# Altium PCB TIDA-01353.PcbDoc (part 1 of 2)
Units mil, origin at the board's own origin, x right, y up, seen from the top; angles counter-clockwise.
Board outline 6000 x 6000 mil, 2 copper layers (Top Layer, Bottom Layer), stack 61.6 mil thick; 250 components, 122 nets, 562 pads, 165 vias.
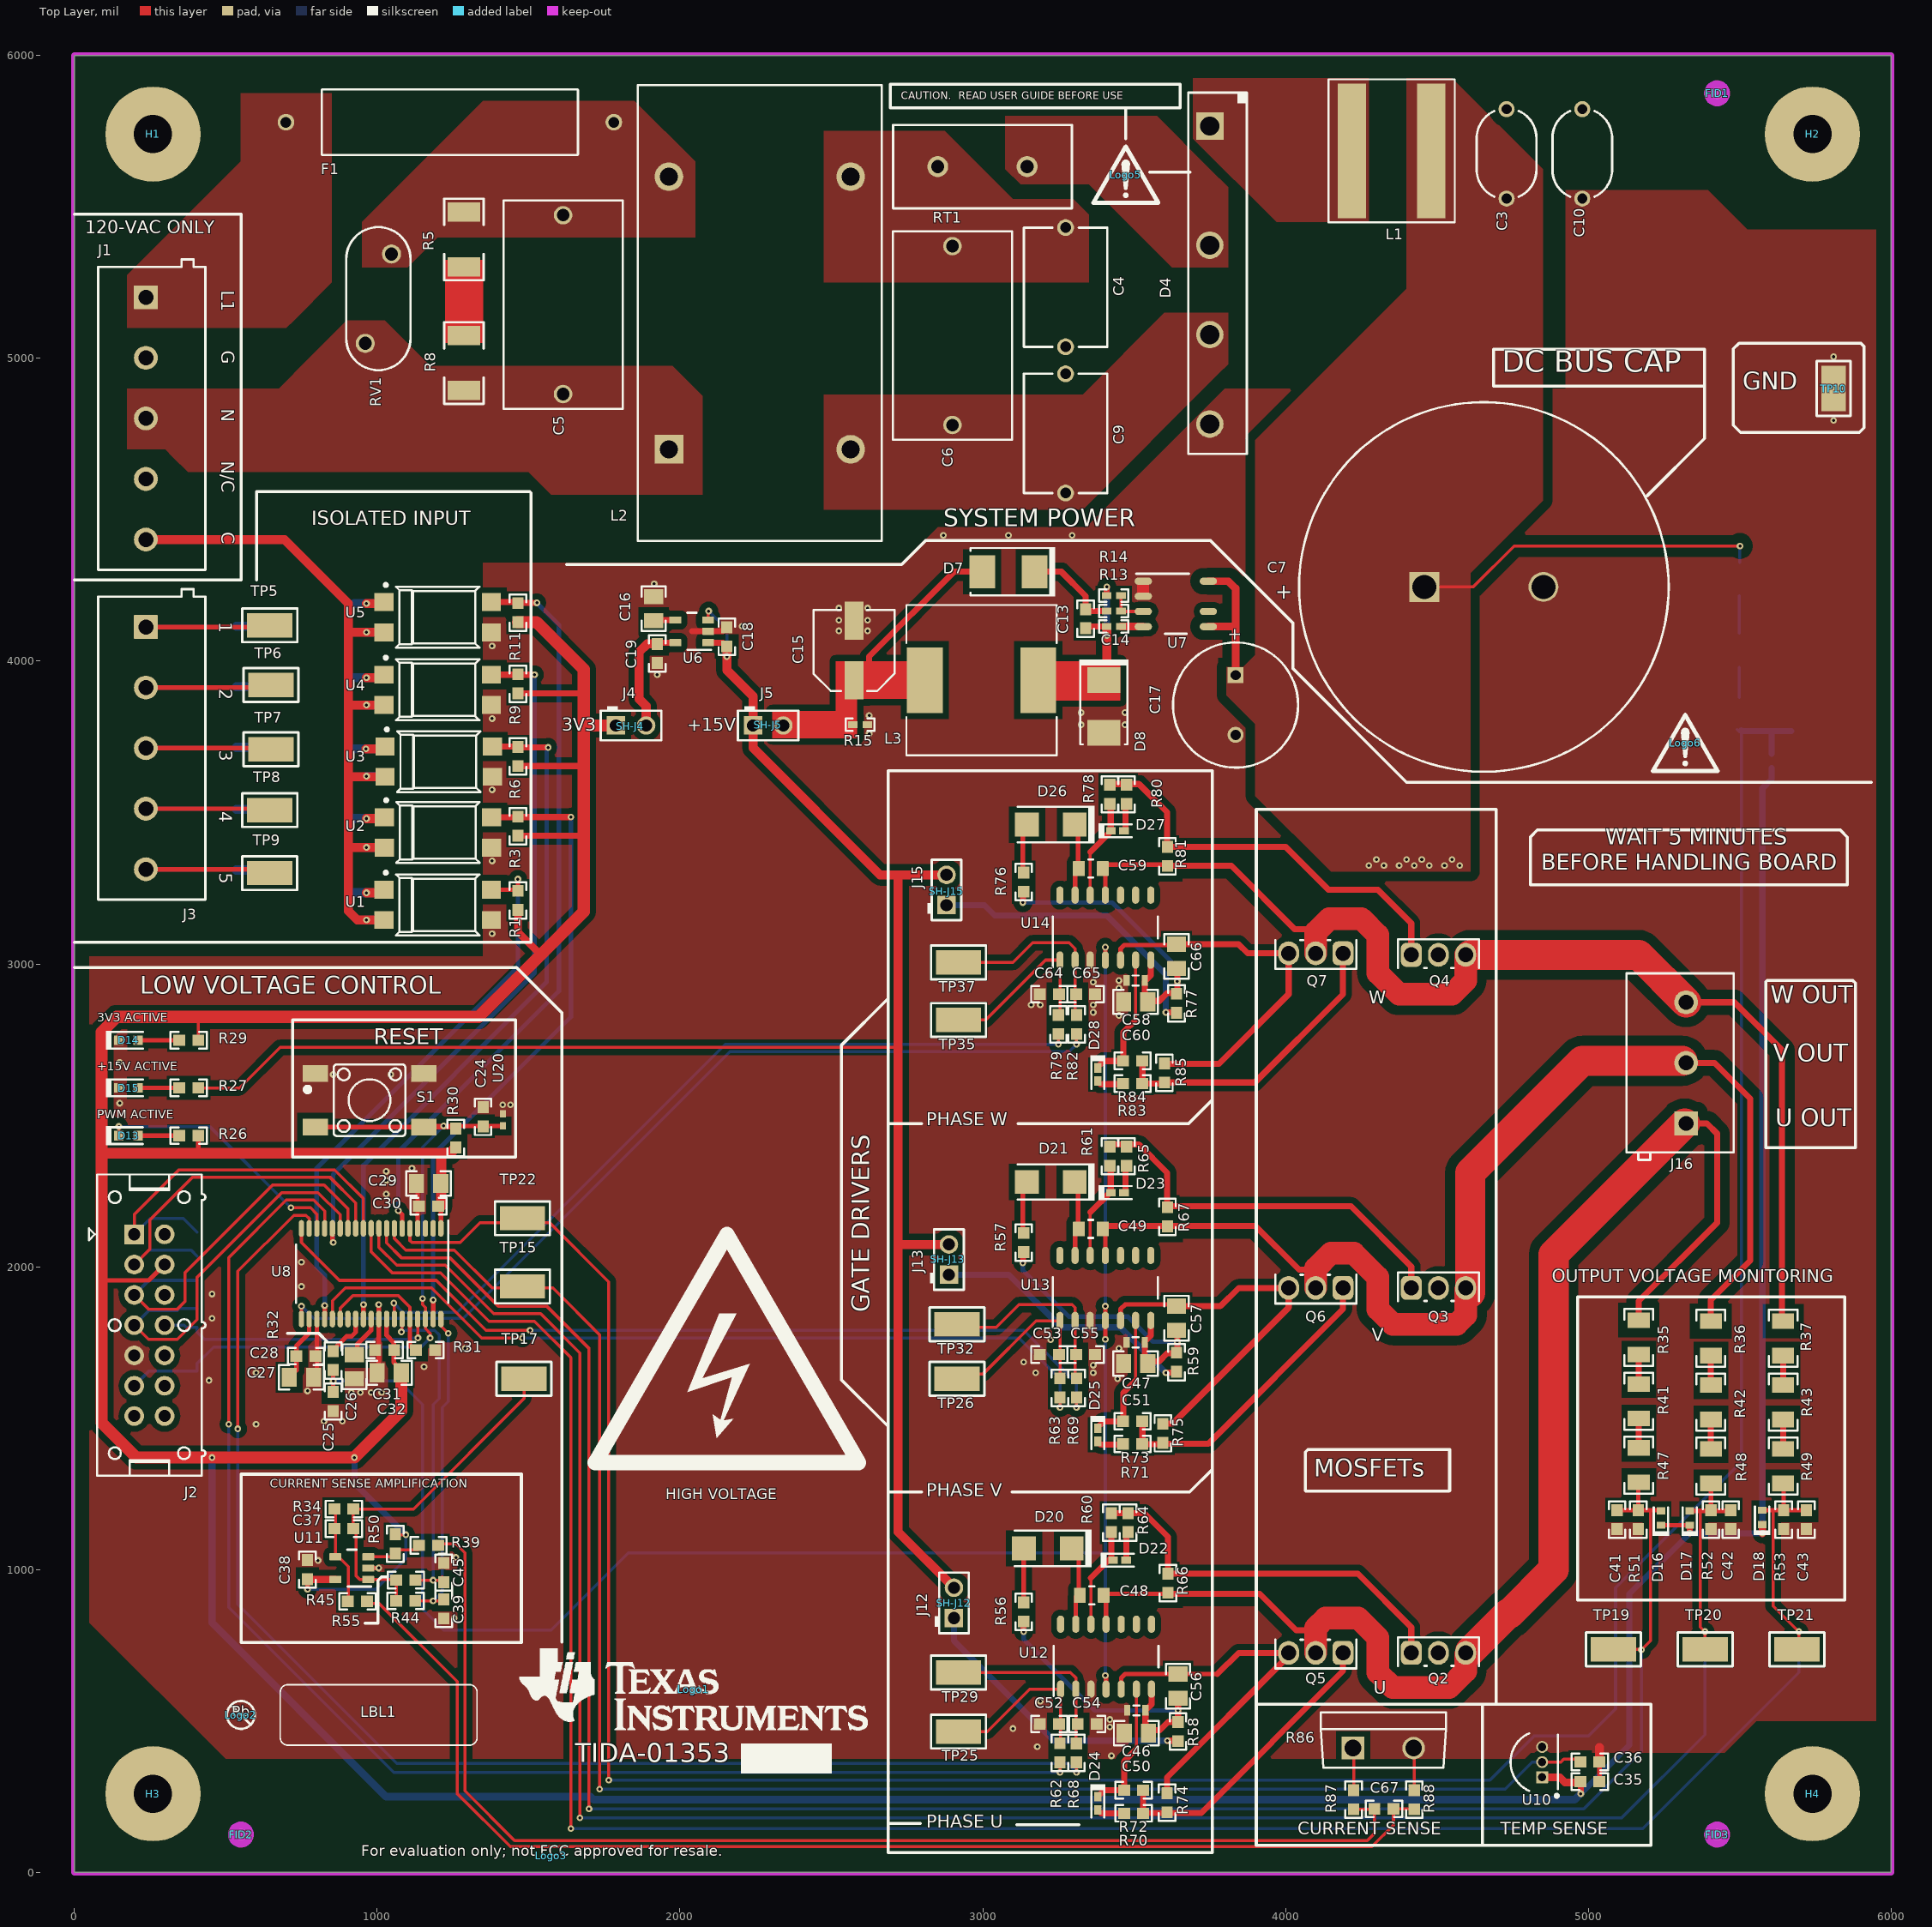
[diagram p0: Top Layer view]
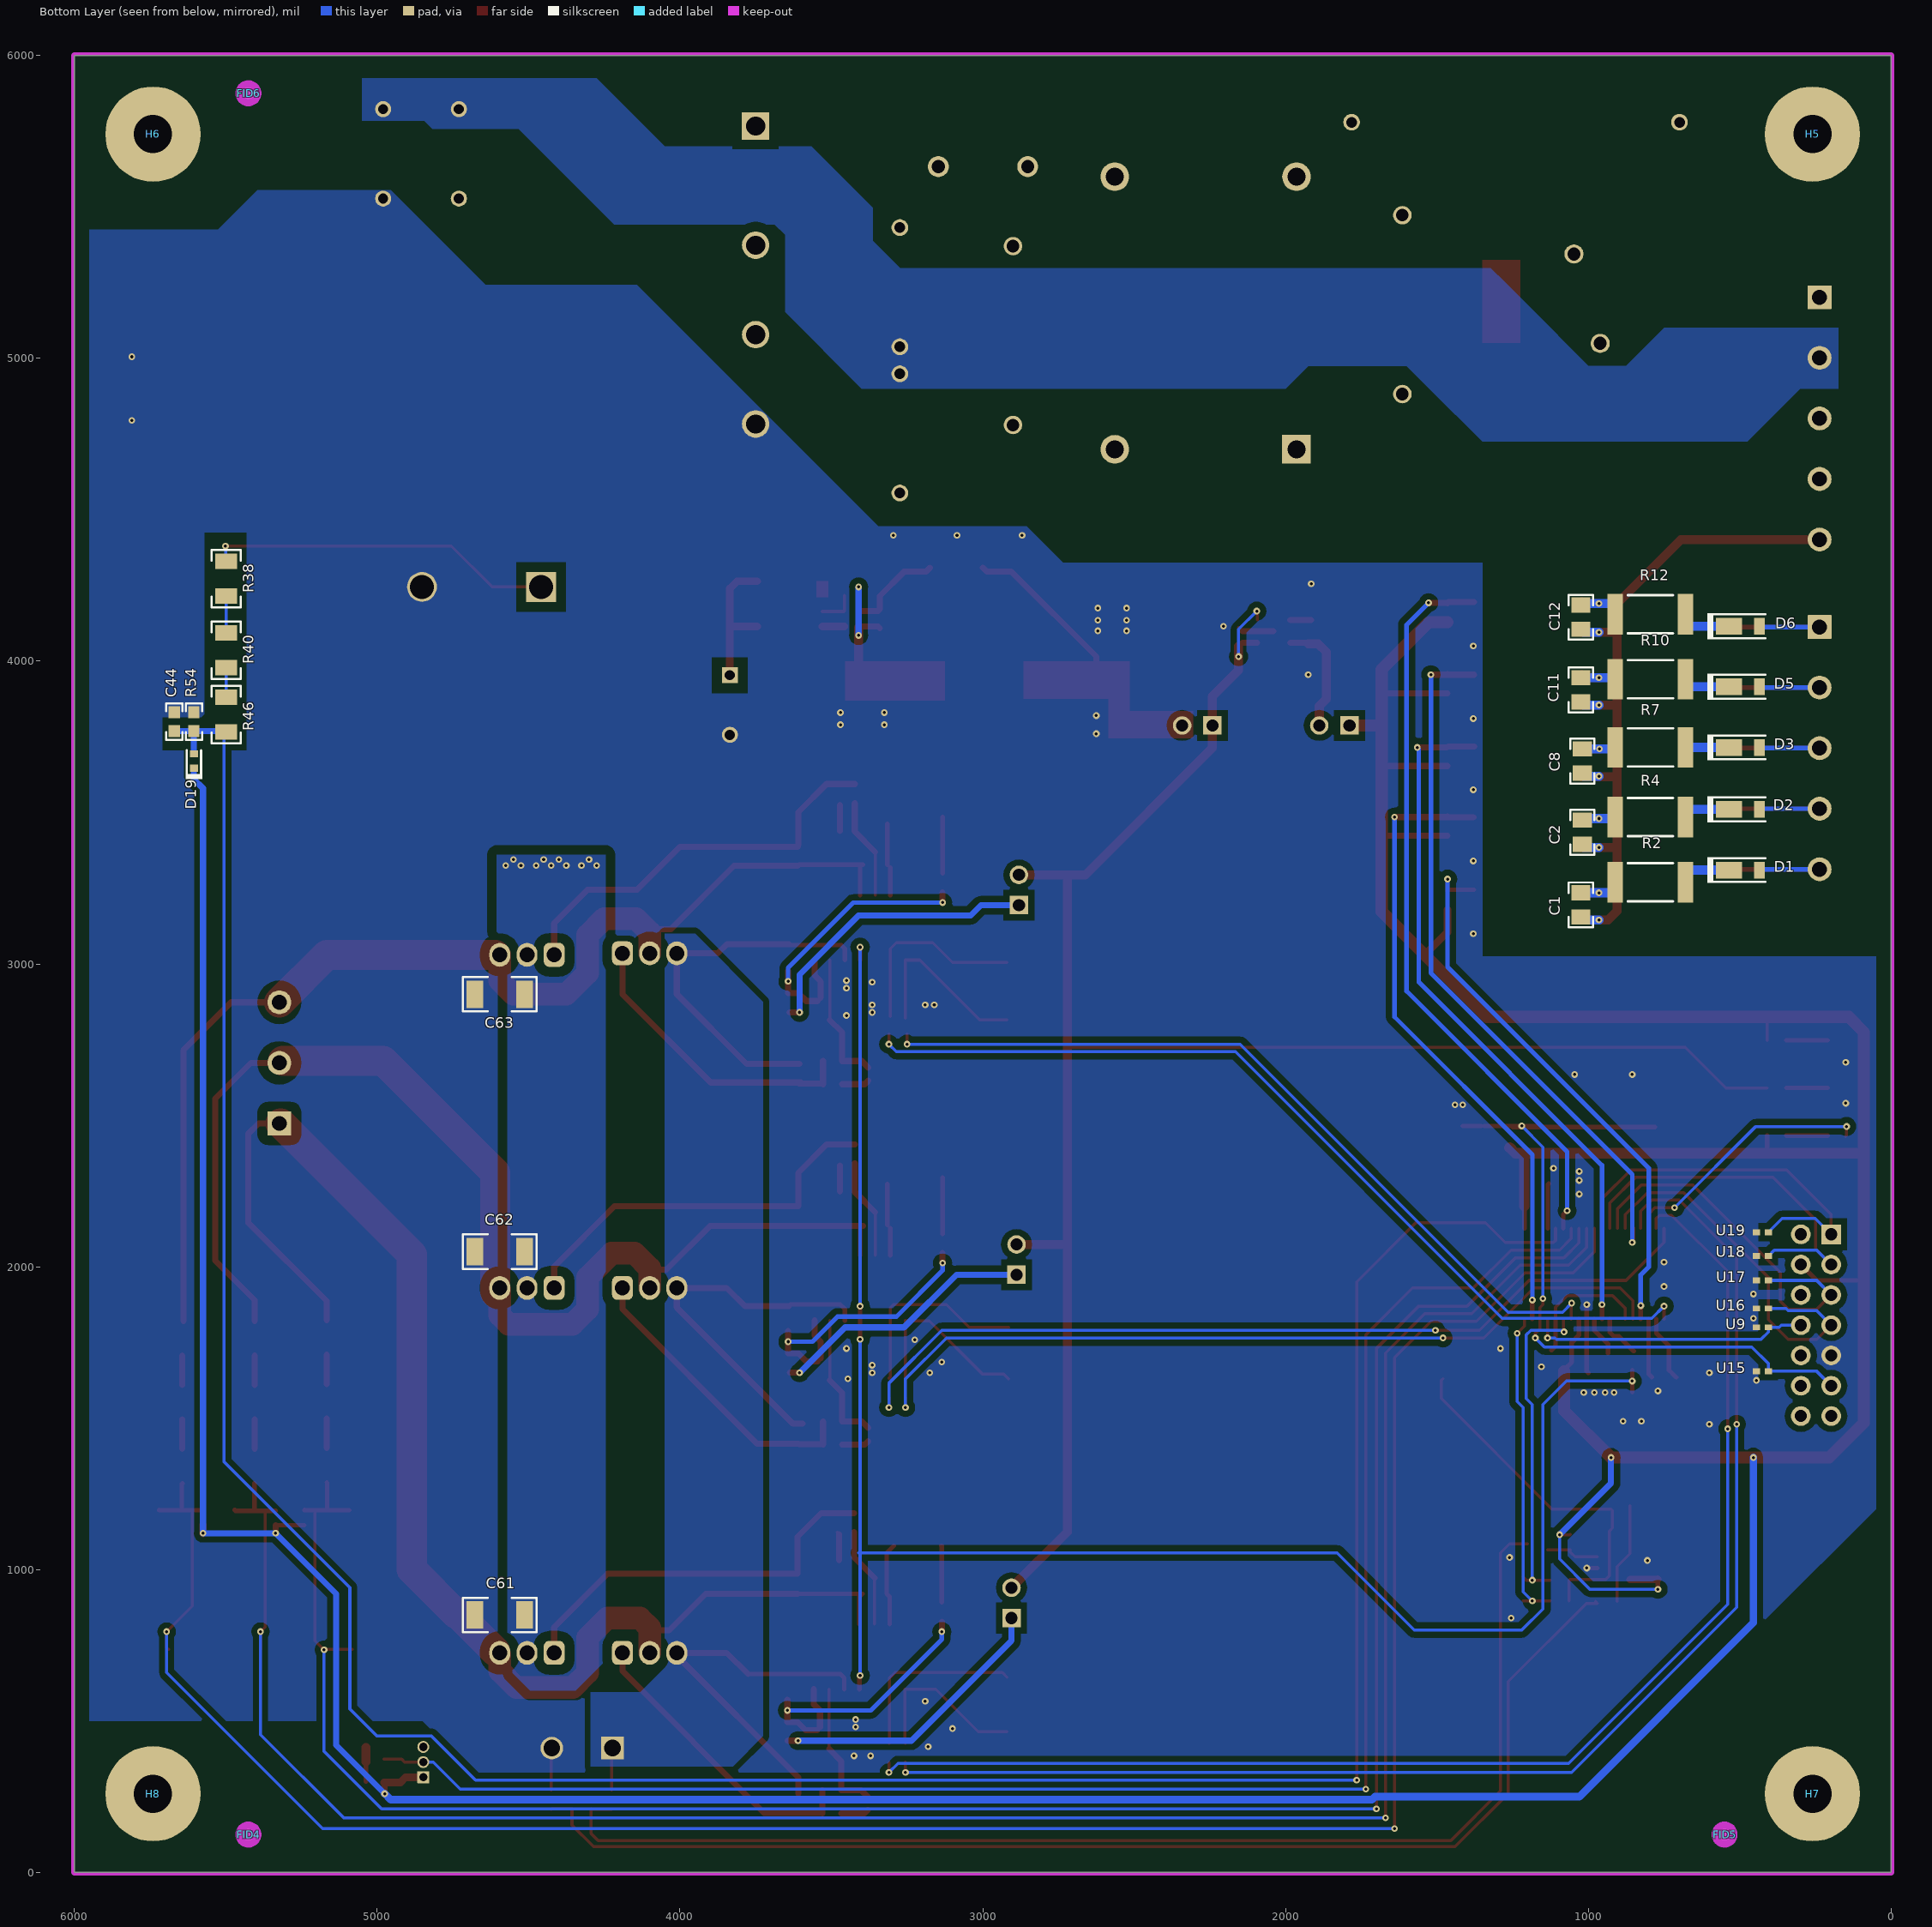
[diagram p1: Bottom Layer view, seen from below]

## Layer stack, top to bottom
Top Solder: solder mask 0.4, Solder Resist, Dk 3.5
Top Layer: signal copper 2.8
Dielectric1: core 56, FR-4 High TG, Dk 4.8
Bottom Layer: signal copper 2.8
Bottom Solder: solder mask 0.4, Solder Resist, Dk 3.5

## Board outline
0,0 0,6000 6000,6000 6000,0

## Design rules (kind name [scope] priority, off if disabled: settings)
AcuteAngle [All] p1: minimum=4.50000000000000E+0001 checktracksonly=FALSE
AssemblyTestPointUsage [All] p1: valid=2
BoardOutlineClearance BoardOutlineClearance_MountingHoles [OnCopper and InComponentClass('Mounting Holes')] p1: gap=40
BoardOutlineClearance BoardOutlineClearance_Poly [OnCopper and IsPoly] p2: gap=25
BoardOutlineClearance [OnCopper and Not InComponentClass('Logo') and not InComponentClass('FiducialMark') and not InRegion(1000,500,4000,800) and not InPoly] p3: gap=50
Clearance Clearance_Keepouts [((IsTrack Or IsArc) And Not InPoly) And IsFree and IsKeepOut vs ((IsTrack Or IsArc) And Not InPoly) And IsFree and IsKeepOut] p1: gap=0
Clearance Clearance_HV [InNet('VDC_LINK') or InNet('PHU') or InNet('PHV') or InNet('PHW') or InNet('E_GND')] p2: gap=16 except(32: Arc-Poly Track-Poly SMDPad-Poly THPad-Poly Via-Poly Fill-Poly Poly-Poly)
Clearance Clearance_Poly [InPolygon] p3: gap=20
Clearance [All] p4: gap=7.87
ComponentClearance ComponentClearance_MountingHoles_FiducialMarks [InComponentClass('Mounting Holes') vs InComponentClass('FiducialMark')] p1: gap=50 collisioncheckmode=3 verticalgap=10 showdistances=FALSE
ComponentClearance ComponentClearance_Shunt [InComponentClass('Shunt')] p2: gap=0 collisioncheckmode=3 verticalgap=0 showdistances=FALSE
ComponentClearance ComponentClearance_Logo [InComponentClass('Logo')] p3: gap=50 collisioncheckmode=3 verticalgap=10 showdistances=FALSE
ComponentClearance ComponentClearance_ScrewToNut [(HasFootprint('NY PMS 440 0025 PH')) vs (HasFootprint('Keystone_1902C'))] p4: gap=5 collisioncheckmode=3 verticalgap=10 showdistances=FALSE
ComponentClearance ComponentClearance_MountingHoles [InComponentClass('Mounting Holes')] p5: gap=150 collisioncheckmode=3 verticalgap=100000 showdistances=FALSE
ComponentClearance ComponentClearance_SmallPassives [HasFootprint('0201*') or HasFootprint('0402*') or HasFootprint('0508') or HasFootprint('0603*') or HasFootprint('0612') or HasFootprint('0805*') or HasFootprint('0815*') or HasFootprint('0830*') or HasFootprint('1206*') or HasFootprint('1210*') or HasFootprint('1808*') or HasFootprint('1812*') or HasFootprint('1825*') or HasFootprint('2010*') or HasFootprint('2220*') or HasFootprint('2225*') or HasFootprint('2512*') or HasFootprint('2728*') or HasFootprint('3518*') vs HasFootprint('0201*') or HasFootprint('0402*') or HasFootprint('0508') or HasFootprint('0603*') or HasFootprint('0612') or HasFootprint('0805*') or HasFootprint('0815*') or HasFootprint('0830*') or HasFootprint('1206*') or HasFootprint('1210*') or HasFootprint('1808*') or HasFootprint('1812*') or HasFootprint('1825*') or HasFootprint('2010*') or HasFootprint('2220*') or HasFootprint('2225*') or HasFootprint('2512*') or HasFootprint('2728*') or HasFootprint('3518*')] p6: gap=14.96 collisioncheckmode=3 verticalgap=10 showdistances=FALSE
ComponentClearance ComponentClearance_THtoSMT [IsThruComponent vs IsSMTComponent] p7: gap=40 collisioncheckmode=3 verticalgap=30 showdistances=FALSE
ComponentClearance ComponentClearance_THtoTH [IsThruComponent vs IsThruComponent] p8: gap=30 collisioncheckmode=3 verticalgap=30 showdistances=FALSE
ComponentClearance [All] p9: gap=30 collisioncheckmode=3 verticalgap=10 showdistances=FALSE
DiffPairsRouting [All] p1: maxlimit=100 minlimit=10 mostfreqgap=10 toplayer_minwidth=15 toplayer_maxwidth=15 toplayer_prefwidth=15 bottomlayer_minwidth=15 bottomlayer_maxwidth=15 bottomlayer_prefwidth=15 maxuncoupledlength=1000
FabricationTestPointUsage TestPointUsage [All] p1: valid=2 allowmultiple=FALSE
FabricationTestpoint Testpoint [All] p1: side=3 testpointundercomponent=TRUE minsize=40 maxsize=100 preferedsize=60 minholesize=0 maxholesize=40 preferedholesize=32 testpointgrid=1 allowsidetop=TRUE allowsidebottom=TRUE usegrid=TRUE gridtolerance=0.01
FanoutControl Fanout_LCC [IsLCC] p1: bgadir=Out bgaviamode=Centered fanoutstyle=Auto fanoutdirection=Alternating viagrid=1 // Fanout_LCC (Default Rule)
FanoutControl Fanout_BGA [IsBGA] p2: bgadir=Out bgaviamode=Centered fanoutstyle=Auto fanoutdirection=Alternating viagrid=1 // Fanout_BGA (Default Rule)
FanoutControl Fanout_Default [All] p4: bgadir=Out bgaviamode=Centered fanoutstyle=Auto fanoutdirection=Alternating viagrid=1 // Fanout_Default (Default Rule)
FanoutControl Fanout_Small [(CompPinCount < 5)] p5: bgadir=Out bgaviamode=Centered fanoutstyle=Auto fanoutdirection=OutThenIn viagrid=1 // Fanout_Small (Default Rule)
Height [All] p1 off: minheight=0 maxheight=1000 prefheight=500
HoleSize [All] p1: absolutevalues=TRUE maxlimit=251 minlimit=7.87 maxpercent=80.000 minpercent=20.000
MinimumAnnularRing MinimumAnnularRing_ThermalPadVias [IsVia and InAnyComponent] p1: minimumring=5.91
MinimumAnnularRing [All] p2: minimumring=5.9
MinimumSolderMaskSliver MinimumSolderMaskSliver_Logo [InComponentClass('Logo') vs InComponentClass('Logo')] p1: minsoldermaskwidth=0.7
MinimumSolderMaskSliver [All] p2: minsoldermaskwidth=3.94
PlaneConnect [All] p1: planeconnectstyle=Relief reliefexpansion=10 reliefentries=4 reliefconductorwidth=10 reliefairgap=10
PolygonConnect [All] p1: connectstyle=Direct reliefconductorwidth=10 reliefentries=4 polygonreliefangle="90 Angle" airgapwidth=10
RoutingVias ThermalPadVias [IsVia and InAnyComponent] p1: holewidth=7.87 width=19.68 viastyle="Through Hole" minholewidth=7.87 minwidth=19.68 maxholewidth=12.99 maxwidth=23.62
RoutingVias [All] p2: holewidth=10 width=26 viastyle="Through Hole" minholewidth=7.87 minwidth=22 maxholewidth=40 maxwidth=65
SilkToBoardRegionClearance [Not ((IsComment or IsDesignator) And (Hide <> 'False')) and not InRegion(1000,500,4000,800)] p1:
SilkToSilkClearance SilkToSilkClearance_Pb-FreeLogo [(HasFootprint('Pb-Free_Overlay_Medium') OR HasFootprint('Pb-Free_Overlay_Small')) vs (HasFootprint('Pb-Free_Overlay_Medium') OR HasFootprint('Pb-Free_Overlay_Small'))] p1: silktosilkclearance=0
SilkToSilkClearance [All] p2: silktosilkclearance=4
SilkToSolderMaskClearance SilkToComponentPadClearance [IsPad and InAnycomponent] p1: minsilkscreentomaskgap=4 clearancetoexposedcopper=TRUE
SilkToSolderMaskClearance "Silk to Solder Mask Opening" [All] p2: minsilkscreentomaskgap=4 clearancetoexposedcopper=FALSE
SolderMaskExpansion [All] p1: expansion=1.97
Width [All] p1: maxlimit=100 minlimit=10 preferedwidth=10 checkconnectedcopper=TRUE
14 further rules are at their usual default settings.

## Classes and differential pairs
component class Shunt: SH-J4 SH-J5 SH-J12 SH-J13 SH-J15
component class "TIDA-01353_System Power": C1 C2 C3 C4 C5 C6 C7 C8 C9 C10 C11 C12 C13 C14 C15 C16 C17 C18 C19 D1 D2 D3 D4 D5 D6 D7 D8 F1 J1 J3 J4 J5 J16 L1 L2 L3 R1 R2 R3 R4 R5 R6 R7 R8 R9 R10 R11 R12 R13 R14 R15 RT1 RV1 SH-J4 SH-J5 TP5 TP6 TP7 TP8 TP9 TP10 U1 U2 U3 U4 U5 U6 U7
component class "TIDA-01353_Motor Control": C46 C47 C48 C49 C50 C51 C52 C53 C54 C55 C56 C57 C58 C59 C60 C61 C62 C63 C64 C65 C66 C67 D20 D21 D22 D23 D24 D25 D26 D27 D28 J12 J13 J15 Q2 Q3 Q4 Q5 Q6 Q7 R56 R57 R58 R59 R60 R61 R62 R63 R64 R65 R66 R67 R68 R69 R70 R71 R72 R73 R74 R75 R76 R77 R78 R79 R80 R81 R82 R83 R84 R85 R86 R87 R88 SH-J12 SH-J13 SH-J15 TP25 TP26 TP29 TP32 TP35 TP37 U12 U13 U14
component class "TIDA-01353_MCU and Peripherals": C24 C25 C26 C27 C28 C29 C30 C31 C32 C35 C36 C37 C38 C39 C41 C42 C43 C44 C45 D13 D14 D15 D16 D17 D18 D19 J2 R26 R27 R29 R30 R31 R32 R34 R35 R36 R37 R38 R39 R40 R41 R42 R43 R44 R45 R46 R47 R48 R49 R50 R51 R52 R53 R54 R55 S1 TP15 TP17 TP19 TP20 TP21 TP22 U8 U9 U10 U11 U15 U16 U17 U18 U19 U20
component class Label: LBL1
component class AssemblyNote: ZZ1 ZZ2 ZZ3 ZZ4
component class FiducialMark: FID1 FID2 FID3 FID4 FID5 FID6
component class TIDA-01353_EVM_Hardware: FID1 FID2 FID3 FID4 FID5 FID6 H1 H2 H3 H4 H5 H6 H7 H8 "HIGH VOLTAGE" LBL1 Logo1 Logo2 Logo3 Logo5 Logo6 ZZ1 ZZ2 ZZ3 ZZ4
component class Logo: Logo1
component class "Mounting Holes": H1 H2 H3 H4

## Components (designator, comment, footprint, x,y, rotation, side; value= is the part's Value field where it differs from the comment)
C1 "08055C105KAT2A" 0805_HV 1025,3195 r270 bottom
C2 "08055C105KAT2A" 0805_HV 1020,3435 r270 bottom
C3 "VY2102M29Y5UG63V7" CAPRD750W60D750H1050 4730,5675 r90 top
C4 "DE1E3KX332MN4AP01F" KX_1000x700 3273.67,5234.73 r270 top
C5 "BFC233840334" CAPRR1500W80D1750T1000H1650 1614.17,5177.17 r270 top
C6 "BFC233840334" CAPRR1500W80D1750T1000H1650 2900,5075 r270 top
C7 "381LR102M200K032" 381LR_3000x3500 4655,4245 r0 top locked
C8 "08055C105KAT2A" 0805_HV 1020,3670 r270 bottom
C9 "DE1E3KX332MN4AP01F" KX_1000x700 3273.67,4751.97 r270 top
C10 "VY2102M29Y5UG63V7" CAPRD750W60D750H1050 4980,5675 r270 top
C11 "08055C105KAT2A" 0805_HV 1025,3905 r270 bottom
C12 "08055C105KAT2A" 0805_HV 1025,4145 r270 bottom
C13 "C0603C104K5RACTU" 0603 3340,4140 r270 top
C14 "GRM155R61A104KA01D" 0402 3433.07,4114.17 r180 top
C15 "EEE-FK1V101XP" SM_RADIAL_D8 2575,4035 r90 top
C16 "C0805C103K5RACTU" 0805_HV 1913.39,4173.23 r90 top
C17 "UCY2G100MPD1TD" CY_1000x1600 3835,3855 r270 top
C18 "GRM188R61E105KA12D" 0603 2155,4080 r90 top
C19 "GRM188R60J475KE19D" 0603 1925,4025 r270 top
C24 "C0603C222K5RAC" 0603 1350,2495 r90 top
C25 "06035A221FAT2A" 0603 855,1555 r270 top
C26 "C0805C474K4RACTU" 0805_HV 925,1670 r270 top
C27 "0805YD106MAT2A" 0805_HV 750,1635 r0 top
C28 "0603YC104JAT2A" 0603 765,1705 r0 top
C29 "0805YD106MAT2A" 0805_HV 1170,2275 r180 top
C30 "0603YC104JAT2A" 0603 1170,2200 r180 top
C31 "0603YC104JAT2A" 0603 1025,1725 r180 top
C32 "0805YD106MAT2A" 0805_HV 1040,1650 r180 top
C35 "0603YC104JAT2A" 0603 5005,300 r180 top
C36 "0603YC104JAT2A" 0603 5005,365 r180 top
C37 "06035A100JAT2A" 0603 890,1135 r180 top
C38 "0603YC104JAT2A" 0603 770,1000 r90 top
C39 "GRM188R61H102KA01D" 0603 1220,870 r90 top
C41 "06035A100JAT2A" 0603 5095,1165 r270 top
C42 "06035A100JAT2A" 0603 5470,1165 r270 top
C43 "06035A100JAT2A" 0603 5720,1165 r270 top
C44 "06035A330JAT2A" 0603 5670,3800 r90 bottom
C45 "GRM188R61H102KA01D" 0603 1220,990 r270 top
C46 "06033C104JAT2A" 0603S 3507.32,535 r180 top
C47 "06033C104JAT2A" 0603S 3505,1750 r180 top
C48 "GRM21BR71E104KA01L" 0805_HV1 3360,915 r0 top
C49 "GRM21BR71E104KA01L" 0805_HV1 3357,2125 r0 top
C50 "GRM21BR71E105KA99L" 0805_HV 3507.32,460 r180 top
C51 "GRM21BR71E105KA99L" 0805_HV 3505,1680 r180 top
C52 "06035A221FAT2A" 0603 3220,490 r180 top
C53 "06035A221FAT2A" 0603 3220,1710 r180 top
C54 "06035A221FAT2A" 0603 3345,490 r0 top
C55 "06035A221FAT2A" 0603 3340,1710 r0 top
C56 "GRM21BR71E105KA99L" 0805_HV 3645,615 r270 top
C57 "GRM21BR71E105KA99L" 0805_HV 3640,1830 r270 top
C58 "06033C104JAT2A" 0603S 3505,2945 r180 top
C59 "GRM21BR71E104KA01L" 0805_HV1 3357,3315 r0 top
C60 "GRM21BR71E105KA99L" 0805_HV 3505,2875 r180 top
C61 "VJ1808Y104KXPAT5Z" 1808 4595,850 r0 bottom
C62 "VJ1808Y104KXPAT5Z" 1808 4595,2050 r0 bottom
C63 "VJ1808Y104KXPAT5Z" 1808 4595,2900 r0 bottom
C64 "06035A221FAT2A" 0603 3220,2900 r180 top
C65 "06035A221FAT2A" 0603 3340,2900 r0 top
C66 "GRM21BR71E105KA99L" 0805_HV 3640,3025 r270 top
C67 "GRM188R61H102KA01D" 0603 4325,210 r0 top
D1 "SBRT3U40P1-7" PowerDI123 485,3310 r180 bottom
D2 "SBRT3U40P1-7" PowerDI123 485,3510 r180 bottom
D3 "SBRT3U40P1-7" PowerDI123 485,3715 r180 bottom
D4 "GBJ3502-BP" GBJ 3750,5275 r270 top
D5 "SBRT3U40P1-7" PowerDI123 485,3915 r180 bottom
D6 "SBRT3U40P1-7" PowerDI123 485,4115 r180 bottom
D7 "MURS140-13-F" SMB 3085,4295 r180 top
D8 "MURS140-13-F" SMB 3400,3850 r270 top
D13 "150060RS75000" WL-SMCW_RED 178.54,2433.07 r0 top
D14 "150060BS75000" WL-SMCW_Blue 178.54,2748.03 r0 top
D15 "150060VS75000" WL-SMCW_GREEN 178.54,2590.55 r0 top
D16 "CDBP0130L-G" SOD-723 5240,1170 r90 top
D17 "CDBP0130L-G" SOD-723 5335,1170 r90 top
D18 "CDBP0130L-G" SOD-723 5573.97,1172.4 r90 top
D19 "CDBP0130L-G" SOD-723 5605,3670 r90 bottom
D20 "US1M-13-F" SMA 3215,1070 r180 top
D21 "US1M-13-F" SMA 3225,2280 r180 top
D22 "SDM20U40-7-F" SOD-523 3452.09,1031.11 r0 top
D23 "SDM20U40-7-F" SOD-523 3445,2245 r0 top
D24 "SDM20U40-7-F" SOD-523 3379.84,228.35 r270 top
D25 "SDM20U40-7-F" SOD-523 3380,1445 r270 top
D26 "US1M-13-F" SMA 3225,3460 r180 top
D27 "SDM20U40-7-F" SOD-523 3445,3440 r0 top
D28 "SDM20U40-7-F" SOD-523 3380,2635 r270 top
F1 "0217015.MXEP" Fuse_217_015 1240.32,5779.53 r180 top
FID1 "Fiducial" Fiducial10-20 5425,5875 r0 top
FID2 "Fiducial" Fiducial10-20 550,125 r0 top
FID3 "Fiducial" Fiducial10-20 5425,125 r0 top
FID4 "Fiducial" Fiducial10-20 5425,125 r90 bottom
FID5 "Fiducial" Fiducial10-20 550,125 r90 bottom
FID6 "Fiducial" Fiducial10-20 5425,5875 r90 bottom
H1 "NY PMS 440 0025 PH" "NY PMS 440 0025 PH"#1 260,5740 r0 top locked
H2 "NY PMS 440 0025 PH" "NY PMS 440 0025 PH"#1 5740,5740 r0 top locked
H3 "NY PMS 440 0025 PH" "NY PMS 440 0025 PH"#2 259.24,260.01 r0 top locked
H4 "NY PMS 440 0025 PH" "NY PMS 440 0025 PH"#1 5740,260 r0 top locked
H5 "1902C" Keystone_1902C 260,5740 r180 bottom locked
H6 "1902C" Keystone_1902C 5740,5740 r180 bottom locked
H7 "1902C" Keystone_1902C 260,260 r180 bottom locked
H8 "1902C" Keystone_1902C 5740,260 r180 bottom locked
"HIGH VOLTAGE" "DANGER HIGH VOLTAGE" IEC_HighVoltage_Large 2155,1705 r0 top
J1 "ED120/5DS" On-Shore_ED120_5DS 236.22,4801.41 r270 top
J2 "SBH11-PBPC-D07-ST-BK" CONN_SBH11-PBPC-D07-ST-BK 248.03,1807.09 r270 top
J3 "ED120/5DS" On-Shore_ED120_5DS 236.22,3712.6 r270 top
J4 "HTSW-102-09-G-S" Samtec_HTSW-102-09-x-S 1838.58,3787.4 r0 top
J5 "HTSW-102-09-G-S" Samtec_HTSW-102-09-x-S 2291.34,3787.4 r0 top
J12 "HTSW-102-09-G-S" Samtec_HTSW-102-09-x-S 2905,890 r90 top
J13 "HTSW-102-09-G-S" Samtec_HTSW-102-09-x-S 2888.31,2023.62 r90 top
J15 "HTSW-102-09-G-S" Samtec_HTSW-102-09-x-S 2880.43,3244.09 r90 top
J16 "ED120/3DS" On-Shore_ED120_3DS 5322.83,2673.23 r90 top
L1 "XAL1010-103MEB" XAL1010 4350.39,5685.04 r0 top
L2 "8114-RC" 8100_8109-8114 2263.78,5149.61 r90 top
L3 "MSS1210-185KE" MSS1210 2996.06,3937.01 r180 top
LBL1 "Size: 0.65\" x 0.20 \"" Label_650x200 1005,520 r0 top
Logo1 "Texas Instruments" TI_Stacked_Overlay_Medium 2045,605 r0 top
Logo2 "Pb-Free Symbol" Pb-Free_Overlay_Small 550,520 r0 top
Logo3 "FCC disclaimer" FCC_disclaimer 1575,55 r0 top
Logo5 "CAUTION.  READ USER GUIDE BEFORE USE" IEC_Caution_Small 3472.44,5606.3 r0 top
Logo6 "CAUTION.  READ USER GUIDE BEFORE USE" IEC_Caution_Small 5320,3730 r0 top
Q2 "IRFU13N20DPBF" IPAK 4505,725 r0 top
Q3 "IRFU13N20DPBF" IPAK 4505,1930 r0 top
Q4 "IRFU13N20DPBF" IPAK 4505,3030 r0 top
Q5 "IRFU13N20DPBF" IPAK 4100,725 r180 top
Q6 "IRFU13N20DPBF" IPAK 4100,1930 r180 top
Q7 "IRFU13N20DPBF" IPAK 4100,3035 r180 top
R1 "CRCW060347K0JNEA" 0603 1465,3210 r270 top
R2 "CRCW25128K25FKEG" 2512 795,3270 r0 bottom
R3 "CRCW060347K0JNEA" 0603 1465,3455 r270 top
R4 "CRCW25128K25FKEG" 2512 795,3485 r0 bottom
R5 "CRCW2010499KFKEF" 2010 1286.67,5392.32 r90 top
R6 "CRCW060347K0JNEA" 0603 1465,3685 r270 top
R7 "CRCW25128K25FKEG" 2512 795,3715 r0 bottom
R8 "CRCW2010499KFKEF" 2010 1286.67,4984.25 r90 top
R9 "CRCW060347K0JNEA" 0603 1465,3925 r270 top
R10 "CRCW25128K25FKEG" 2512 795,3940 r0 bottom
R11 "CRCW060347K0JNEA" 0603 1465,4160 r270 top
R12 "CRCW25128K25FKEG" 2512 795,4155 r0 bottom
R13 "CRCW0402143KFKED" 0402 3433.07,4165.35 r180 top
R14 "CRCW040210K2FKED" 0402 3433.07,4216.54 r0 top
R15 "CRCW040215K0FKED" 0402 2595,3790 r180 top
R26 "CRCW06035K11FKEA" 0603 377.95,2433.07 r180 top
R27 "CRCW06032K55FKEA" 0603 377.95,2590.55 r180 top
R29 "CRCW060320R0FKEA" 0603 377.95,2748.03 r0 top
R30 "CRCW060347K0JNEA" 0603 1260,2425 r270 top
R31 "CRCW060347K0JNEA" 0603 1160,1725 r180 top
R32 "CRCW0603100RFKEA" 0603 855,1690 r270 top
R34 "RC0603FR-078K87L" 0603 890,1200 r180 top
R35 "CRCW120668K1FKEA" 1206 5166.73,1766.8 r90 top
R36 "CRCW120668K1FKEA" 1206 5404.69,1763.59 r90 top
R37 "CRCW120668K1FKEA" 1206 5643.3,1763.59 r90 top
R38 "RC1206FR-07226KL" 1206 5498.35,4272.24 r90 bottom
R39 "RT0603BRD073K28L" 0603 1170,1080 r180 top
R40 "RC1206FR-07226KL" 1206 5498.35,4036.02 r90 bottom
R41 "CRCW120668K1FKEA" 1206 5166.73,1555.85 r90 top
R42 "CRCW120668K1FKEA" 1206 5404.69,1552.64 r90 top
R43 "CRCW120668K1FKEA" 1206 5643.3,1552.64 r90 top
R44 "CRCW0603100RFKEA" 0603 1094.56,896.65 r180 top
R45 "CRCW060315K0FKEA" 0603 935,895 r180 top
R46 "RC1206FR-07226KL" 1206 5498.35,3823.43 r90 bottom
R47 "CRCW120668K1FKEA" 1206 5166.73,1344.91 r90 top
R48 "CRCW120668K1FKEA" 1206 5404.69,1341.69 r90 top
R49 "CRCW120668K1FKEA" 1206 5643.3,1341.69 r90 top
R50 "RG1608P-103-B-T5" 0603 1060,1085 r270 top
R51 "CRCW06033K60JNEA" 0603 5165,1165 r90 top
R52 "CRCW06033K60JNEA" 0603 5405,1165 r90 top
R53 "CRCW06033K60JNEA" 0603 5645,1165 r90 top
R54 "RC0603FR-0712KL" 0603 5605,3800 r270 bottom
R55 "CRCW0603100RFKEA" 0603 1095,965 r180 top
R56 "CRCW06033R30JNEA" 0603 3135,860 r90 top
R57 "CRCW06033R30JNEA" 0603 3135,2080 r90 top
R58 "RC0603FR-075R11L" 0603 3645,465 r270 top
R59 "RC0603FR-075R11L" 0603 3640,1685 r270 top
R60 "CRCW060310R0FKEAHP" 0603 3425,1155 r90 top
R61 "CRCW060310R0FKEAHP" 0603 3420,2365 r90 top
R62 "CRCW060351R1FKEA" 0603 3255,395 r90 top
R63 "CRCW060351R1FKEA" 0603 3255,1600 r90 top
R64 "RC0603FR-075R11L" 0603 3480,1155 r90 top
R65 "RC0603FR-075R11L" 0603 3475,2365 r90 top
R66 "CRCW060320K0FKEA" 0603 3611.5,955 r90 top
R67 "CRCW060320K0FKEA" 0603 3610,2165 r90 top
R68 "CRCW060351R1FKEA" 0603 3309.57,394.78 r90 top
R69 "CRCW060351R1FKEA" 0603 3310,1600 r90 top
R70 "RC0603FR-075R11L" 0603 3498.34,195.22 r0 top
R71 "RC0603FR-075R11L" 0603 3495,1415 r0 top
R72 "CRCW060310R0FKEAHP" 0603 3498.34,271.65 r0 top
R73 "CRCW060310R0FKEAHP" 0603 3495,1490 r0 top
R74 "CRCW060320K0FKEA" 0603 3608.78,230 r270 top
R75 "CRCW060320K0FKEA" 0603 3595,1450 r270 top
R76 "CRCW06033R30JNEA" 0603 3135,3270 r90 top
R77 "RC0603FR-075R11L" 0603 3640,2870 r270 top
R78 "CRCW060310R0FKEAHP" 0603 3420,3560 r90 top
R79 "CRCW060351R1FKEA" 0603 3250,2800 r90 top
R80 "RC0603FR-075R11L" 0603 3475,3560 r90 top
R81 "CRCW060320K0FKEA" 0603 3610,3355 r90 top
R82 "CRCW060351R1FKEA" 0603 3310,2800 r90 top
R83 "RC0603FR-075R11L" 0603 3495,2605 r0 top
R84 "CRCW060310R0FKEAHP" 0603 3495,2680 r0 top
R85 "CRCW060320K0FKEA" 0603 3600,2640 r270 top
R86 "PWR220T-20-R100F" TO-220AC 4323.06,410.32 r0 top
R87 "CRCW0603100RFKEA" 0603 4225,240 r90 top
R88 "CRCW0603100RFKEA" 0603 4425,240 r90 top
RT1 "B57237S229M" S237 2999,5632.85 r0 top
RV1 "S10K275E2" VAR_S10K275E2 1004.1,5196.85 r90 top
S1 "4-1437565-1" SW_FSM4JSMA 975,2550 r90 top
SH-J4 "969102-0000-DA" SNT-100-BK-G 1835,3785 r0 top
SH-J5 "969102-0000-DA" SNT-100-BK-G 2290,3790 r0 top
SH-J12 "969102-0000-DA" SNT-100-BK-G 2905,890 r90 top
SH-J13 "969102-0000-DA" SNT-100-BK-G 2885,2025 r90 top
SH-J15 "969102-0000-DA" SNT-100-BK-G 2880,3240 r90 top
TP5 "TESTPOINT" Keystone_5019 645.67,4118.11 r0 top
TP6 "TESTPOINT" Keystone_5019 649.61,3921.26 r0 top
TP7 "TESTPOINT" Keystone_5019 649.61,3708.66 r0 top
TP8 "TESTPOINT" Keystone_5019 645.67,3507.87 r0 top
TP9 "TESTPOINT" Keystone_5019 645,3300 r0 top
TP10 "TESTPOINT" Keystone_5019 5810,4900 r90 top
TP15 "TESTPOINT" Keystone_5019 1480,1935 r0 top
TP17 "TESTPOINT" Keystone_5019 1485,1630 r0 top
TP19 "TESTPOINT" Keystone_5019 5082.68,736.65 r0 top
TP20 "TESTPOINT" Keystone_5019 5385.83,736.65 r0 top
TP21 "TESTPOINT" Keystone_5019 5688.98,736.65 r0 top
TP22 "TESTPOINT" Keystone_5019 1480,2160 r0 top
TP25 "TESTPOINT" Keystone_5019 2920,465 r180 top
TP26 "TESTPOINT" Keystone_5019 2915,1630 r180 top
TP29 "TESTPOINT" Keystone_5019 2920,660 r180 top
TP32 "TESTPOINT" Keystone_5019 2915,1810 r180 top
TP35 "TESTPOINT" Keystone_5019 2920,2815 r0 top
TP37 "TESTPOINT" Keystone_5019 2920,3005 r0 top
U1 "LTV-817S" DIP254P762X350-4#1 1200,3195 r0 top
U2 "LTV-817S" DIP254P762X350-4#2 1020,3190 r0 top
U3 "LTV-817S" DIP254P762X350-4#3 1430,3660 r180 top
U4 "LTV-817S" DIP254P762X350-4#1 1200,3905 r0 top
U5 "LTV-817S" DIP254P762X350-4#1 1200,4145 r0 top
U6 "LP2985-33DBVR" DBV0005A_N 2039.06,4098.43 r180 top
U7 "UCC28881DR" D0007A_N 3637.61,4188.98 r0 top
U8 "MSP430F5132IDA" DA0038A_N 980.32,1977.05 r270 top
U9 "TPD1E10B06DPYR" DPY0002A 425,1800 r0 bottom
U10 "LMT84" LP0003A_straight 4847.44,364.25 r180 top
U11 "TLV316IDBVR" DBV0005A_N 916.37,1004.74 r180 top
U12 "UCC27714DR" D0014A_N 3407.31,712.44 r90 top
U13 "UCC27714DR" D0014A_N 3405,1930 r90 top
U14 "UCC27714DR" D0014A_N 3405,3120 r90 top
U15 "TPD1E10B06DPYR" DPY0002A 425,1655 r0 bottom
U16 "TPD1E10B06DPYR" DPY0002A 425.2,1862.2 r0 bottom
U17 "TPD1E10B06DPYR" DPY0002A 425,1955 r0 bottom
U18 "TPD1E10B06DPYR" DPY0002A 425.2,2035.43 r0 bottom
U19 "TPD1E10B06DPYR" DPY0002A 425.2,2114.17 r0 bottom
U20 "TPD1E10B06DPYR" DPY0002A 1415,2485 r270 top
ZZ1 "This Assembly Note is for PCB labels only" AssemblyNoteLabel 314.96,6629.92 r0 top
ZZ2 "These assemblies are ESD sensitive, ESD precautions shall be observed." AssemblyNote 314.96,6535.43 r0 top
ZZ3 "These assemblies must be clean and free from flux and all contaminants. Use of no clean flux is not acceptable." AssemblyNote 314.96,6444.88 r0 top
ZZ4 "These assemblies must comply with workmanship standards IPC-A-610 Class 2, unless otherwise specified." AssemblyNote 314.96,6358.27 r0 top

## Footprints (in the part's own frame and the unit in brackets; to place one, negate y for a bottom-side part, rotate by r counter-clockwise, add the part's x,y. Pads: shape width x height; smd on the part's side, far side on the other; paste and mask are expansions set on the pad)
381LR_3000x3500 [mm] "TH, 2-Leads, Dia 30mm, Pin Spacing 10mm"
  rect 2.5x2.5 hole 2: 1(-5,0)
  round 2.5 hole 2: 2(5,0)
  silkscreen extent -15.5,-15.5 15.5,15.5, body extent -15.5,-15.5 15.51,15.5, height 37.01
0402 [mm] "0402 from SM-752 data"
  rect 0.8x0.6 smd: 1(-0.6,0) 2(0.6,0)
  silkscreen extent -1.22,-0.52 1.22,0.52, body extent -0.55,-0.3 0.55,0.3, height 0.6
0603 [mm] "0603 from SM-752 data"
  rect 1x0.95 smd: 1(-0.8,0) 2(0.8,0)
  silkscreen extent -1.52,-0.69 1.52,0.69, body extent -0.87,-0.47 0.87,0.47, height 1
0603S [mil]
  rect 20x35 smd: 1(-30,0) 2(30,0)
  silkscreen extent -10,-17 10,17, body extent -34,-19 34,19, height 39
0805_HV [mil] "0805 with 30mil clearance between pads"
  rect 50x63 smd: 1(-40,0) 2(40,0)
  silkscreen extent -74,-40 74,40, body extent -43,-29 43,29, height 57
0805_HV1 [mm] "Custom footprint based on analyzing multiple manufacturer recommendations"
  rrect10% 1x1.25 smd: 1(-1,0) 2(1,0)
  silkscreen extent -0.2,-0.75 0.2,0.75, body extent -1.1,-0.72 1.1,0.73, height 1.45
1206 [mm] "1206 from SM-752 data"
  rect 1.3x1.85 smd: 1(-1.45,0) 2(1.45,0)
  silkscreen extent -2.4,-1.21 2.4,1.21, body extent -1.7,-0.9 1.7,0.9, height 1.35
1808 [mm] "Chip Capacitor, Body 4.6x2.0mm, IPC Medium Density"
  rect 1.4x2.3 smd: 1(-2.1,0) 2(2.1,0)
  silkscreen extent -3.1,-1.45 3.1,1.45, body extent -2.47,-1.2 2.47,1.2, height 2.03
2010 [mm] "Chip Capacitor, Body 5.08x2.54mm, IPC Medium Density"
  rect 1.6x2.7 smd: 1(-2.3,0) 2(2.3,0)
  silkscreen extent -3.42,-1.65 3.42,1.65, body extent -2.73,-1.45 2.73,1.45, height 1.66
2512 [mm] "Chip Resistor, Body 6.3x3.2mm, IPC Medium Density"
  rect 1.3x3.4 smd: 1(-2.95,0) 2(2.95,0)
  silkscreen extent -1.9,-1.6 1.9,1.6, body extent -3.22,-1.67 3.22,1.67, height 0.71
8100_8109-8114 [mm] "Bourns, Power Inductor"
  rect 2.4x2.4 hole 1.5: 1(-11.43,7.62)
  round 2.4 hole 1.5: 2(-11.43,-7.62) 3(11.43,-7.62) 4(11.43,7.62)
  silkscreen extent -19.11,-10.22 19.11,10.22, body extent -17.78,-10.03 17.4,10.03, height 38.1
AssemblyNote [mil] "Assembly Note"
AssemblyNoteLabel [mil] "Assembly Note for PCB Labels"
CAPRD750W60D750H1050 [mm] "Vishay BC Components"
  round 1.35 hole 0.85: 1(-3.75,0) 2(3.75,0)
  silkscreen extent -3.6,-2.51 3.6,2.51, body extent -4.15,-2.5 4.15,2.5, height 11.25
CAPRR1500W80D1750T1000H1650 [mm] "VISHAY/BC COMPONENTS"
  round 1.55 hole 1.05: 1(-7.5,0) 2(7.5,0)
  silkscreen extent -8.75,-5 8.75,5, body extent -8.75,-5 8.75,5, height 16.5
CONN_SBH11-PBPC-D07-ST-BK [mm] "Sullins recommended land pattern"
  rect 1.65x1.65 hole 1.016 mask+0: 1(-7.62,-1.27)
  round 1.65 hole 1.016 mask+0: 2(-7.62,1.27) 3(-5.08,-1.27) 4(-5.08,1.27) 5(-2.54,-1.27) 6(-2.54,1.27) 7(0,-1.27) 8(0,1.27) 9(2.54,-1.27) 10(2.54,1.27) 11(5.08,-1.27) 12(5.08,1.27) 13(7.62,-1.27) 14(7.62,1.27)
  silkscreen extent -12.64,-5.08 12.64,4.7, body extent -12.64,-4.4 12.64,4.7, height 9.12
CY_1000x1600 [mm] "TH, 2-Leads, Dia 10mm, Pitch 5mm"
  rect 1.35x1.35 hole 0.85: 1(-2.5,0)
  round 1.35 hole 0.85: 2(2.5,0)
  silkscreen extent -5.25,-5.25 5.25,5.25, body extent -5.2,-5.23 5.25,5.25, height 17.5
D0007A_N [mm] "SOIC, 7-Leads, Body 4.9x3.9mm, Pitch 1.27mm, IPC Medium Density"
  oval 1.45x0.6 smd: 1(-2.725,1.905) 2(-2.725,0.635) 3(-2.725,-0.635) 4(-2.725,-1.905) 5(2.725,-1.905) 6(2.725,-0.635) 8(2.725,1.905)
  silkscreen extent -3.33,-2.5 1.1,2.52, body extent -3.01,-2.45 3.01,2.45, height 1.75
D0014A_N [mm] "SOIC, 14-Leads, Body 8.7x3.9mm, Pitch 1.27mm, IPC Medium Density"
  oval 1.45x0.6 smd: 1(-2.725,3.81) 2(-2.725,2.54) 3(-2.725,1.27) 4(-2.725,0) 5(-2.725,-1.27) 6(-2.725,-2.54) 7(-2.725,-3.81) 8(2.725,-3.81) 9(2.725,-2.54) 10(2.725,-1.27) 11(2.725,0) 12(2.725,1.27) 13(2.725,2.54) 14(2.725,3.81)
  silkscreen extent -3.3,-4.4 0.9,4.4, body extent -3.02,-4.32 3.02,4.32, height 1.6
DA0038A_N [mm] "TSOP, 38-Leads, Body 12.6x6.2mm (max), Pitch 0.65mm, IPC Medium Density"
  oval 1.4x0.45 smd: 1(-3.8,5.85) 2(-3.8,5.2) 3(-3.8,4.55) 4(-3.8,3.9) 5(-3.8,3.25) 6(-3.8,2.6) 7(-3.8,1.95) 8(-3.8,1.3) 9(-3.8,0.65) 10(-3.8,0) 11(-3.8,-0.65) 12(-3.8,-1.3) 13(-3.8,-1.95) 14(-3.8,-2.6) 15(-3.8,-3.25) 16(-3.8,-3.9) 17(-3.8,-4.55) 18(-3.8,-5.2) 19(-3.8,-5.85) 20(3.8,-5.85) 21(3.8,-5.2) 22(3.8,-4.55) 23(3.8,-3.9) 24(3.8,-3.25) 25(3.8,-2.6) 26(3.8,-1.95) 27(3.8,-1.3) 28(3.8,-0.65) 29(3.8,0) 30(3.8,0.65) 31(3.8,1.3) 32(3.8,1.95) 33(3.8,2.6) 34(3.8,3.25) 35(3.8,3.9) 36(3.8,4.55) 37(3.8,5.2) 38(3.8,5.85)
  silkscreen extent -4.45,-6.3 2.45,6.47, body extent -4.06,-6.25 4.06,6.25, height 1.2
DBV0005A_N [mm] "SOT23, 5-Leads, Body 2.9x1.6mm, Pitch 0.95mm, Lead Span 2.8mm, IPC Medium Density"
  rrect17% 1x0.6 smd: 1(-1.375,0.95) 2(-1.375,0) 3(-1.375,-0.95) 4(1.375,-0.95) 5(1.375,0.95)
  silkscreen extent -1.63,-1.55 0.38,1.55, body extent -1.42,-1.46 1.42,1.46, height 1.09
DIP254P762X350-4#1 [mm] "LITE-ON"
  rect 1.6x1.5 smd: 1(-4.5,1.27) 2(-4.5,-1.27) 3(4.5,-1.27) 4(4.5,1.27)
  silkscreen extent -4.47,-2.55 3.5,2.82, body extent -5.23,-2.55 5.23,2.55, height 4.62
DIP254P762X350-4#2 [mm] "LITE-ON"
  rect 1.6x1.5 smd: 1(0.1,7.47) 2(0.1,4.93) 3(9.1,4.93) 4(9.1,7.47)
  silkscreen extent 0.13,3.65 8.1,9.02, body extent -0.63,3.65 9.83,8.75, height 4.62
DIP254P762X350-4#3 [mm] "LITE-ON"
  rect 1.6x1.5 smd: 1(10.249,-1.47) 2(10.249,1.07) 3(1.249,1.07) 4(1.249,-1.47)
  silkscreen extent 2.25,-3.02 10.22,2.35, body extent 0.52,-2.75 10.98,2.35, height 4.62
DPY0002A [mm] "R-PX2SON-N2"
  rect 0.6x0.5 smd: 1(-0.5,0) 2(0.5,0)
  body extent -0.55,-0.35 0.55,0.35, height 0.4
FCC_disclaimer [mil]
Fiducial10-20 [mm]
  round 1 smd mask+0.5: 1(0,0)
  Top Layer keep-out circle w1.178: c0,0 r0.5
Fuse_217_015 [mm] "TH, 2-Leads, Body 21.5x5.5mm, Pin Spacing 27.5mm"
  round 1.4 hole 0.9: 1(-13.75,0) 2(13.75,0)
  silkscreen extent -10.75,-2.75 10.75,2.75, body extent -14.07,-2.75 14.08,2.75, height 5.5
GBJ [mm] "Micro Commercial Components"
  rect 2.3x2.3 hole 1.6: 1(-12.5,0)
  round 2.3 hole 1.6: 2(-2.5,0) 3(5,0) 4(12.5,0)
  silkscreen extent -15.3,-1.8 15,3.1, body extent -15.25,-1.75 15.05,3.05, height 24.3
IEC_Caution_Small [mil]
  silkscreen extent -107,-93 107,92
IEC_HighVoltage_Large [mil]
  silkscreen extent -435,-352 435,401
IPAK [mm] "IPAK"
  rrect50% 1.75x2 hole 1.25: 1(-2.28,0)
  oval 1.75x2 hole 1.25: 2(0,0) 3(2.28,0)
  silkscreen extent -3.4,-1.1 3.4,1.3, body extent -3.25,-0.99 3.25,1.31, height 9.66
Keystone_1902C [mil] "Hex Standoff, 4-40 threaded, nylon"
  body extent -145,-126 146,126, height 501
Keystone_5019 [mm] "Test Point, Miniature, SMT"
  rect 3.8x2.03 smd: 1(0,0)
  silkscreen extent -2.31,-1.41 2.31,1.42, body extent -1.9,-1.02 1.9,1.02, height 2.29
KX_1000x700 [mm] "TH, 2-Leads, Dia 10mm, Lead Spacing 10mm"
  round 1.4 hole 0.9: 1(-5,0) 2(5,0)
  silkscreen extent -5,-3.5 5,3.5, body extent -5.32,-3.5 5.33,3.5, height 12.99
Label_650x200 [mil] "Thermal Transfer Label"
  silkscreen extent -325,-100 325,100, body extent -325,-100 325,100, height 1
LP0003A_straight [mm] "TH, 3-Leads, Pin Spacing 1.27mm"
  rrect7% 1x1 hole 0.7: 1(0,1.27)
  round 1 hole 0.7: 2(0,0) 3(0,-1.27)
  silkscreen extent -1.35,-2.41 2.65,2.95, body extent -1.34,-2.41 2.35,2.41, height 6.84
MSS1210 [mm] "Coilcraft MSS1210 series"
  rect 3x5.5 smd: 1(-4.75,0) 2(4.75,0)
  silkscreen extent -6.3,-6.3 6.3,6.3, body extent -6.15,-6.15 6.15,6.15, height 10.2
"NY PMS 440 0025 PH"#1 [mm] "4-40 nylon screw and mounting hole"
  round 8 hole 3.2: 1(0,0)
  body extent -3.3,-3.3 3.3,3.3, height 2.69
"NY PMS 440 0025 PH"#2 [mm] "4-40 nylon screw and mounting hole"
  round 8 hole 3.2: 1(0.019,0)
  body extent -3.3,-3.3 3.3,3.3, height 2.69
On-Shore_ED120_3DS [mm] "ONSHORE"
  rrect5% 2x2 hole 1.25: 1(-5.08,0)
  round 2 hole 1.25: 2(0,0) 3(5.08,0)
  silkscreen extent -8.14,-4 7.5,5, body extent -8.32,-4 7.62,5, height 13
On-Shore_ED120_5DS [mm] "TH, 5-Leads, Body 25.4x9mm, Pitch 5.08mm"
  rrect5% 2x2 hole 1.25: 1(-10.16,0)
  round 2 hole 1.25: 2(-5.08,0) 3(0,0) 4(5.08,0) 5(10.16,0)
  silkscreen extent -13.34,-4 12.7,5, body extent -13.4,-4 12.7,5, height 13
Pb-Free_Overlay_Small [mil]
  silkscreen extent -46,-46 46,46
PowerDI123 [mm] "Diodes Inc recommended land pattern, document number DS30628 Rev. 6-2"
  rect 2.2x1.4 smd: 1(-1.275,0)
  rect 0.9x1.4 smd: 2(1.275,0)
  silkscreen extent -3.1,-1.09 1.76,1.09, body extent -2.37,-0.96 1.53,0.97, height 1
S237 [mm] "EPCOS"
  round 1.75 hole 1.1: 1(-3.75,0) 2(3.75,0)
  silkscreen extent -7.5,-3.5 7.5,3.5, body extent -7.47,-3.5 7.47,3.5, height 21.99
Samtec_HTSW-102-09-x-S [mm] "Header, 2x1, 2.54mm, TH"
  rect 1.55x1.55 hole 1.02: 1(-1.27,0)
  round 1.55 hole 1.02: 2(1.27,0)
  silkscreen extent -2.54,-1.24 2.54,1.6, body extent -2.54,-1.24 2.54,1.24, height 8.38
SM_RADIAL_D8 [mm] "6.3 x 7.7mm:  Panasonic D8"
  rect 3.2x1.6 smd: 1(-2.5,0) 2(2.5,0)
  silkscreen extent -3.4,-3.4 3.4,3.4, body extent -3.4,-3.4 3.4,3.4, height 8.01
SMA [mm] "Molded Diode, 2-Leads, Body 4.3x2.6mm, IPC Medium Density, based on OnSemi component dimensions and land pattern"
  rect 2x2 smd: 1(-2,0) 2(2,0)
  silkscreen extent -3.66,-1.57 2.79,1.57, body extent -2.6,-1.3 2.6,1.3, height 2.42
SMB [mil] "Molded Diode, 2-Leads, Body 5.4x3.6mm, IPC Medium Density, based on OnSemi component dimensions"
  rect 85x107.99 smd: 1(-87.01,0) 2(87.01,0)
  silkscreen extent -155,-82 125,82, body extent -106,-71 106,71, height 91
SNT-100-BK-G [mil] "Samtec STEP model"
  round 1 on Mech3: 0(0,0)
  body extent -100,-50 100,50, height 344
SOD-523 [mm] "NXP Semiconductor recommended land pattern, nominal STEP model"
  rect 0.8x0.6 smd paste-0.05: 1(-0.55,0) 2(0.55,0)
  silkscreen extent -1.6,-0.64 1.2,0.63, body extent -0.8,-0.4 0.8,0.4, height 0.72
SOD-723 [mm] "SMD, 2-Leads, Body 1x0.6mm"
  rect 0.6x0.7 smd: 1(-0.6,0) 2(0.6,0)
  silkscreen extent -1.5,-0.7 0.9,0.7, body extent -0.75,-0.33 0.75,0.33, height 0.65
SW_FSM4JSMA [mm] "Alcoswitch"
  rect 1.4x2.1 smd: 1(2.25,4.55) 2(2.25,-4.55) 3(-2.25,4.55) 4(-2.25,-4.55)
  silkscreen extent -3,-3 3,5.4, body extent -3,-5 3,5, height 5.1
TI_Stacked_Overlay_Medium [mil]
  silkscreen extent -576,-136 576,134
TO-220AC [mm]
  rect 1.9x1.9 hole 1.4: 1(-2.54,0)
  round 1.9 hole 1.4: 3(2.54,0)
  silkscreen extent -5.25,-1.64 5.26,3.01, body extent -5.25,-1.64 5.26,3.01, height 19.09
VAR_S10K275E2 [mm] "EPCOS"
  round 1.6 hole 1.1: 1(-3.75,1.1) 2(3.75,-1.1)
  silkscreen extent -6,-2.7 6,2.7, body extent -5.98,-2.7 5.98,2.7, height 14.99
WL-SMCW_Blue [mm] "SMD, 2-Leads, Body 1.6x0.8mm"
  rect 0.8x0.8 smd: 1(-0.8,0) 2(0.8,0)
  silkscreen extent -1.9,-0.8 1.2,0.8, body extent -0.85,-0.45 0.85,0.45, height 0.8
WL-SMCW_GREEN [mm] "WURTH"
  rect 0.8x0.8 smd: 1(-0.8,0) 2(0.8,0)
  silkscreen extent -1.9,-0.8 1.2,0.8, body extent -0.85,-0.45 0.85,0.45, height 0.8
WL-SMCW_RED [mm] "WURTH"
  rect 0.8x0.8 smd: 1(-0.8,0) 2(0.8,0)
  silkscreen extent -1.9,-0.8 1.2,0.8, body extent -0.85,-0.45 0.85,0.45, height 0.8
XAL1010 [mm] "COILCRAFT"
  rect 2.38x11.31 smd: 1(-3.325,0) 2(3.325,0)
  silkscreen extent -5.3,-6 5.3,6, body extent -5.25,-5.9 5.25,5.9, height 10

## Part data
C1 C2 C8 C11 C12: "CAP, CERM, 1 µF, 50 V, +/- 10%, X7R, 0805"
C3 C10: "CAP, CERM, 1000 pF, 300 V, +/- 20%, Y5U, Radial Disc 7.5mm, ls=7.5"
C4 C9: "CAP, CERM, 3300 pF, 300 V, +/- 20%, E, D10xT7mm"
C5 C6: "CAP, Film, 0.33 µF, 630 V, +/- 20%, TH"
C7: "CAP, AL, 1000 µF, 200 V, +/- 20%, 0.149 ohm, TH"
C13: "CAP, CERM, 0.1 µF, 50 V, +/- 10%, X7R, 0603"
C14: "CAP, CERM, 0.1 µF, 10 V, +/- 10%, X5R, 0402"
C15: "CAP, AL, 100 µF, 35 V, +/- 20%, 0.34 ohm, AEC-Q200 Grade 2, SMD"
C16: "CAP, CERM, 0.01 µF, 50 V, +/- 10%, X7R, 0805"
C17: "CAP, AL, 10 µF, 400 V, +/- 20%,  ohm, TH"
C18: "CAP, CERM, 1 µF, 25 V, +/- 10%, X5R, 0603"
C19: "CAP, CERM, 4.7 µF, 6.3 V, +/- 10%, X5R, 0603"
C24: "CAP, CERM, 2200 pF, 50 V, +/- 10%, X7R, 0603"
C25 C52 C53 C54 C55 C64 C65: "CAP, CERM, 220 pF, 50 V, +/- 1%, C0G/NP0, 0603"
C26: "CAP, CERM, 0.47 µF, 16 V, +/- 10%, X7R, 0805"
C27 C29 C32: "CAP, CERM, 10uF, 16V, +/-20%, X5R, 0805"
C28 C30 C31 C35 C36: "CAP, CERM, 0.1 µF, 16 V, +/- 5%, X7R, 0603"
C37 C41 C42 C43: "CAP, CERM, 10 pF, 50 V, +/- 5%, C0G/NP0, 0603"
C38: "CAP, CERM, 0.1uF, 16V, +/-5%, X7R, 0603"
C39 C45 C67: "CAP, CERM, 1000 pF, 50 V, +/- 10%, X5R, 0603"
C44: "CAP, CERM, 33 pF, 50 V, +/- 5%, C0G/NP0, 0603"
C46 C47 C58: "CAP, CERM, 0.1 µF, 25 V, +/- 5%, X7R, 0603"
C48 C49 C59: "CAP, CERM, 0.1 µF, 25 V, +/- 10%, X7R, 0805"
C50 C51 C56 C57 C60 C66: "CAP, CERM, 1 µF, 25 V, +/- 10%, X7R, 0805"
C61 C62 C63: "CAP, CERM, 0.1 µF, 250 V, +/- 10%, X7R, 1808"
D1 D2 D3 D5 D6: "Diode, Super Barrier Rectifier, 40 V, 3 A, AEC-Q101, PowerDI123"
D4: "Diode, P-N-Bridge, 200 V, 35 A, TH"
D7 D8: "Diode, Ultrafast, 400 V, 1 A, SMB"
D13: "LED, Red, SMD"
D14: "LED, Blue, SMD"
D15: "LED, Green, SMD"
D16 D17 D18 D19: "Diode, Schottky, 30 V, 0.1 A, SOD-723"
D20 D21 D26: "Diode, Ultrafast, 1000 V, 1 A, SMA"
D22 D23 D24 D25 D27 D28: "Diode, Schottky, 40 V, 0.25 A, SOD-523"
F1: "Fuse, 15 A, 250 VDC, TH"
FID1 FID2 FID3 FID4 FID5 FID6: "Fiducial mark.  There is nothing to buy or mount."
H1 H2 H3 H4: "Machine Screw, Round, #4-40 x 1/4, Nylon, Philips panhead"
H5 H6 H7 H8: "Standoff, Hex, 0.5\"L #4-40 Nylon"
"HIGH VOLTAGE": library part IEC_HighVoltage, "IEC 61010-1 High Voltage Warning"
J1 J3: "Terminal Block, 5.08 mm, 5x1, Brass, TH"
J2: "Header (shrouded), 100 mil, 7x2, Gold, TH"
J4 J5 J12 J13 J15: "Header, 100mil, 2x1, Gold, TH"
J16: "Terminal Block, 5.08 mm, 3x1, Brass, TH"
L1: "Inductor, Shielded, Composite, 10 µH, 15.5 A, 0.01 ohm, SMD"
L2: "Coupled inductor, 2.5 mH, 12.5 A, 0.011 ohm, TH"
L3: "Inductor, Shielded, Ferrite, 1.8 mH, 0.79 A, 1.54 ohm, SMD"
LBL1: library part THT-14-423-10, "Thermal Transfer Printable Labels, 0.650\" W x 0.200\" H - 10,000 per roll"
Logo1: library part TI_Logo, "Texas Instrument Corporate Signature"
Logo2: library part Pb-Free
Logo3: library part FCC_disclaimer, "FCC_disclaimer"
Logo5 Logo6: library part IEC_Caution, "IEC 61010-1 Caution Warning"
Q2 Q3 Q4 Q5 Q6 Q7: "MOSFET, N-CH, 200 V, 13 A, IPAK"
R1 R3 R6 R9 R11 R30 R31: "RES, 47k ohm, 5%, 0.1W, 0603"
R2 R4 R7 R10 R12: "RES, 8.25 k, 1%, 1 W, AEC-Q200 Grade 0, 2512"
R5 R8: "RES, 499 k, 1%, 0.75 W, AEC-Q200 Grade 0, 2010"
R13: "RES, 143 k, 1%, 0.063 W, 0402"
R14: "RES, 10.2 k, 1%, 0.063 W, 0402"
R15: "RES, 15.0 k, 1%, 0.063 W, 0402"
R26: "RES, 5.11 k, 1%, 0.1 W, 0603"
R27: "RES, 2.55 k, 1%, 0.1 W, 0603"
R29: "RES, 20.0, 1%, 0.1 W, 0603"
R32 R44 R55 R87 R88: "RES, 100, 1%, 0.1 W, 0603"
R34: "RES, 8.87 k, 1%, 0.1 W, 0603"
R35 R36 R37 R41 R42 R43 R47 R48 R49: "RES, 68.1 k, 1%, 0.25 W, 1206"
R38 R40 R46: "RES, 226 k, 1%, 0.25 W, 1206"
R39: "RES, 3.28 k, 0.1%, 0.1 W, 0603"
R45: "RES, 15.0 k, 1%, 0.1 W, 0603"
R50: "RES, 10.0 k, 0.1%, 0.1 W, 0603"
R51 R52 R53: "RES, 3.6 k, 5%, 0.1 W, 0603"
R54: "RES, 12.0 k, 1%, 0.1 W, 0603"
R56 R57 R76: "RES, 3.3, 5%, 0.1 W, 0603"
R58 R59 R64 R65 R70 R71 R77 R80 R83: "RES, 5.11, 1%, 0.1 W, 0603"
R60 R61 R72 R73 R78 R84: "RES, 10.0, 1%, 0.25 W, 0603"
R62 R63 R68 R69 R79 R82: "RES, 51.1, 1%, 0.1 W, 0603"
R66 R67 R74 R75 R81 R85: "RES, 20.0 k, 1%, 0.1 W, 0603"
R86: "RES, 0.1, 1%, 20 W, TO-220AC"
RT1: "Thermistor NTC, 2.2 ohm, 20%, 15x7mm"
RV1: "Varistor 275V RMS 10MM Radial, TH"
S1: "Switch, Tactile, SPST-NO, 0.05A, 12V, SMT"
SH-J4 SH-J5 SH-J12 SH-J13 SH-J15: "Shunt, 100mil, Gold plated, Black"
TP5 TP6 TP7 TP8 TP9 TP10 TP15 TP17 TP19 TP20 TP21 TP22 TP25 TP26 TP29 TP32 TP35 TP37: library part 5019, "Test Point, Miniature, SMT"
U1 U2 U3 U4 U5: "Optocoupler, 5 kV, 50-600% CTR, SMT"
U6: "100-mA ULTRA-LOW DROPOUT REGULATOR WITH SHUTDOWN, DBV0005A (SOT-5)"
U7: "700-V Lowest Quiescent Current Off-Line Switcher, D0007A (SOIC-7)"
U8: "25 MHz Mixed Signal Microcontroller with 8 KB Flash, 1024 B SRAM and 29 GPIOs, -40 to 85 degC, 38-pin SOP (DA), Green (RoHS & no Sb/Br)"
U9 U15 U16 U17 U18 U19 U20: "ESD in 0402 Package with 10 pF Capacitance and 6 V Breakdown, 1 Channel, -40 to +125 degC, 2-pin X2SON (DPY), Green (RoHS & no Sb/Br)"
U10: library part LMT84LPM, "1.5V, TO-92, Analog Temperature Sensor with Class-AB Output, LP0003A"
U11: "10-MHz, Rail-to-Rail Input/Output, Low-Voltage, 1.8-V CMOS Operational Amplifier, DBV0005A (SOT-5)"
U12 U13 U14: "High-Speed,4A, 600V High-side Low-side Gate Driver Device, D0014A"
ZZ1: library part AssemblyNoteLabel
ZZ2 ZZ3 ZZ4: library part AssemblyNote

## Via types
v1: diameter 22, hole 10, Top Layer to Bottom Layer, tented both sides, 165 vias

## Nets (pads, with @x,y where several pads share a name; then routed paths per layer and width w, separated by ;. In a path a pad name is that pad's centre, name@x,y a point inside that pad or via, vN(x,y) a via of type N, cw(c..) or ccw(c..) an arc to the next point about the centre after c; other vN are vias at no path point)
3V3: C29.1 C30.1 C31.1 C32.1 C35.2 C38.1 D16.1 D17.1 D18.1 D19.1 J2.4 J4.1 R1.2 R3.2 R6.2 R9.2 R11.2 R26.1 R29.2 R30.2 R50.1 U8.1 U8.31 U10.1 U11.5 | length 18642.7
  Top Layer w10: R29.2@410,2747.48 410,2825 ; R50.1@1060,1116.5 1061.5,1115 v1(1095,1115)
  Top Layer w15: 90,1955 245.95,1955 J2.4@298.03,2007.09 ; 409.45,2382.52 R26.1@409.45,2433.07 ; v1(770,935) 770.71,935.71 C38.1@770.71,968.07 ; U8.31@1031.5,1827.44 1031.5,1773.5 1055,1750 1055,1685 C32.1@1080,1660 ; U8.1@1210.63,2126.66 C30.1@1210.63,2197.87 ; D16.1@5240,1146.38 D17.1@5335,1146.38
  Top Layer w20: R3.2@1465,3423.5 1681.1,3423.5 1682.6,3425 ; R6.2@1465,3653.5 1681.1,3653.5 1682.6,3655 ; R9.2@1465,3893.5 1674.1,3893.5 1682.6,3885 ; v1(4975,260) 4975,294.81 C35.2@4977.51,297.32 ; v1(5335,1120) D17.1@5335,1146.38 ; D18.1@5573.97,1148.78 D18.1@5575,1147.75
  Top Layer w25: C38.1@770.71,968.07 771.45,967.33 U11.5@862.23,967.33 ; R1.2@1465,3178.5 1465,3105 1540,3030 ; U10.1@4847.44,314.25 4905.75,314.25 4922.68,297.32 C35.2@4977.51,297.32 ; v1(5575,1120) D18.1@5575,1147.75
  Top Layer w35: 90,2375 1241.5,2375 R30.2@1260,2393.5 ; C30.1@1211.5,2200 1211.5,2375
  Top Layer w40: C32.1@1080,1655 1080,1525 v1(925,1370) 205,1370 90,1485 90,2775 140,2825 1335,2825 1465,2955 ; 1460,2950 1465,2955 ; R11.2@1465,4128.5 1526.5,4128.5 1682.6,3972.4 1682.6,3885 1682.6,3787.4 ; J4.1@1788.58,3787.4 1682.6,3787.4 ; 1465,2955 1540,3030 1682.6,3172.6 1682.6,3425 1682.6,3655 1682.6,3787.4
  Bottom Layer w10: v1(770,935) 995,935 1095,1035 v1(1095,1115)
  Bottom Layer w20: v1(925,1370) 925,1285 v1(1095,1115) ; v1(4975,260) 5135,420 5135,920 v1(5335,1120) v1(5575,1120) 5575,3580 5605,3610 D19.1@5605,3646.38
  Bottom Layer w25: v1(455,1370) 455,825 1030,250 1705,250 1715,240 4955,240 v1(4975,260)
+15V: C18.1 J5.1 J12.2 J13.2 J15.2 R27.1 U6.1 U6.3 | length 6576
  Top Layer w10: R27.1@409.45,2590.55 545.55,2590.55 680,2725 2715,2725 ; U6.3@2093.2,4135.83 2093.2,4163.19 v1(2095,4165) ; C18.1@2142.48,4061.02 C18.1@2155,4048.5
  Top Layer w20: U6.1@2093.2,4061.02 C18.1@2142.48,4061.02
  Top Layer w30: C18.1@2155,4048.5 v1(2155,4015) 2155,3970 2241.34,3883.66 J5.1@2241.34,3787.4 2241.34,3713.66 2660.91,3294.09 J15.2@2880.43,3294.09 2720,3294.09 2720,2073.62 ; J13.2@2888.31,2073.62 2720,2073.62 ; J12.2@2905,940 2720,1125 2720,2073.62
  Bottom Layer w10: v1(2095,4165) 2155,4105 v1(2155,4015)
C: C1.2 C2.2 C8.2 C11.2 C12.2 J1.5 U1.2 U2.2 U3.2 U4.2 U5.2 | length 2638.1
  Top Layer w30: J1.5@236.22,4401.41 693.59,4401.41 905,4190 905,4095 ; U3.2@1021.48,3617.87 907.13,3617.87 905,3620 ; U1.2@1022.83,3145 v1(965,3145) 935,3145 905,3175 905,3385 ; U4.2@1022.83,3855 905,3855 ; U5.2@1022.83,4095 905,4095 ; U2.2@1023.94,3384.09 905.91,3384.09 905,3385 ; 905,3385 905,3620 ; 905,3620 905,3855 ; 905,3855 905,4095
  Bottom Layer w30: v1(965,3145) 1015,3145 C1.2@1025,3155 ; v1(965,3385) C2.2@1015,3385 ; v1(965,3620) C8.2@1015,3620 ; v1(965,3855) C11.2@1015,3855 ; v1(965,4095) C12.2@1015,4095
CSN: C67.2 R45.1 R88.1 | length 4097.5
  Top Layer w10: R45.1@976.5,895 970,888.5 1006.5,888.5 1265,630 1265,260 1440,85 4285,85 4356.5,156.5 C67.2@4356.5,210 4423.5,210 R88.1@4425,208.5
CSP: C67.1 R39.1 R87.1 | length 4118.8
  Top Layer w10: R39.1@1201.5,1085 1260,1085 1290,1055 1290,268.89 1453.89,105 4270,105 4293.5,128.5 C67.1@4293.5,210 4292.01,208.5 R87.1@4225,208.5
E_GND: C3.2 C4.2 C9.1 C10.1 J1.2
ELECTRIC_HEAT: R3.1 U2.4 U8.37 | length 2110.2
  Top Layer w15: U8.37@1185.04,1827.44 v1(1185,1890)
  Top Layer w20: U2.4@1378.27,3484.09 1462.6,3484.09 R3.1@1463.5,3485 ; R3.1@1465,3486.5 R3.1@1463.5,3485 ; v1(1640,3485) R3.1@1463.5,3485
  Bottom Layer w15: v1(1185,1890) 1185,2370 1640,2825 v1(1640,3485)
EMT: C56.1 C57.1 C66.1 Q5.3 Q6.3 Q7.3 R74.1 R75.1 R85.1 R86.1 R87.2 U12.5 U13.5 U14.5 | length 3903.5
  Top Layer w10: R86.1@4223.06,410.32 4225,408.38 R87.2@4225,271.5
  Top Layer w15: U13.5@3455,1822.72 3455,1859.88 3471.12,1876 3634,1876 C57.1@3640,1870 ; U14.5@3455,3012.72 3455,3049.88 3467.68,3062.56 C66.1@3642.68,3062.56 ; U12.5@3457.32,605.16 3457.32,642.32 3470,655 3775,655 ; Q5.3@4010.24,715.24 Q5.3@4010.24,725
  Top Layer w20: R75.1@3595,1481.5 3626.5,1481.5 4010.24,1865.24 Q6.3@4010.24,1930 3845,1930 3785,1870 C57.1@3640,1870 ; R85.1@3605,2670 3780,2670 4010.24,2900.24 Q7.3@4010.24,3035 ; R74.1@3608.78,260 3608.78,313.78 Q5.3@4010.24,715.24 ; C66.1@3640,3065 3844.77,3065 3874.76,3035 Q7.3@4005,3035 ; 3775,655 3845,725 Q5.3@4010.24,725
ENABLE: C25.1 R32.2 U12.4 U13.4 U14.4 | length 5957.6
  Top Layer w15: C25.1@855,1586.5 R32.2@855,1658.5 ; v1(3405,650) 3407.32,647.68 U12.4@3407.32,605.16 ; v1(3405,1760) v1@3405,1865.25 ; U14.4@3405,3012.72 v1(3405,3055.24)
  Bottom Layer w10: v1(855,1622.5) 1072.5,1622.5 1150,1545 1150,870 1220,800 1575,800 1830,1055 3405,1055 ; v1(3405,650) 3405,1055 ; v1(3405,1760) 3405,1055 ; v1(3405,1870) v1(3405,3055.24) ; 3410,1055 3405,1055
GND: C7.2 C10.2 C15.2 C16.2 C17.2 C18.2 C19.2 C24.2 C25.2 C26.2 C27.2 C28.2 C29.2 C30.2 C31.2 C32.2 C35.1 C36.1 C38.2 C39.1 C41.2 C42.2 C43.2 C44.2 C45.1 C46.2 C47.2 C50.2 C51.2 C52.2 C53.2 C54.2 C55.2 C58.2 C60.2 C61.2 C62.2 C63.2 C64.2 C65.2 D4.4 D8.2 D14.1 D15.1 J2.9 R15.1 R31.1 R51.1 R52.1 R53.1 R54.1 R86.3 R88.2 S1.1 S1.2 TP10.1 U1.3 U2.3 U3.3 U4.3 U5.3 U6.2 U7.1 U7.2 U8.4 U8.22 U8.30 U9.2 U10.3 U11.2 U12.3 U13.3 U14.3 U15.2 U16.2 U17.2 U18.2 U19.2 U20.1 | length 992.7
  Top Layer w10: C18.2@2141.93,4098.43 C18.2@2155,4111.5 ; R88.2@4425,271.5 R86.3@4425,408.38
  Top Layer w15: C27.2@790,1635 801.18,1646.18 U8.22@801.18,1827.44 ; U11.2@970.5,1004.74 970.77,1005 v1(1005,1005) ; C32.2@1000,1650 1005.91,1655.91 U8.30@1005.91,1827.44 1005.91,1874.09 v1(1005,1875) ; C29.2@1130,2275 1133.86,2271.14 U8.4@1133.86,2126.66 ; R86.3@4423.06,410.32 R86.3@4425,408.38 ; C35.1@5036.5,300 C36.1@5036.5,376.44
  Top Layer w20: 2040,4098.43 C18.2@2141.93,4098.43
  Top Layer w30: C36.1@5036.5,365 5036.5,411.74
  other v1: 3370,385 3425,385 3180,415 3100,475 3420,480 3420,505 3190,565 1255,840 805,1030 1260,1040 600,1480 825,1490 885,1490 915,1585 945,1585 980,1585 1015,1585 770,1590 445,1625 3445,1630 600,1650 3175,1650 3365,1650 1155,1670 3365,1675 3135,1685 1290,1730 3450,1730 3224.74,1758.7 455,1830 455,1910 750,1935 750,2015 1030,2240 1030,2285 1030,2315 1115,2325 1415,2535 1440,2535 150,2540 855,2635 1045,2635 150,2675 3450,2830 3365,2840 3160,2865 3190,2865 3365,2865 3450,2920 3365,2940 3450,2945 1380,3100 1380,3340 1380,3575 2625,3760 3325,3790 3470,3790 1380,3810 2625,3820 3325,3830 3470,3830 1925,3955 1380,4050 2525,4100 2620,4100 2205,4115 2525,4135 2620,4135 2525,4175 2620,4175 1915,4255 2870,4415 3085,4415 3295,4415 5810,4795 5810,5005
HIGH: R6.1 U3.4 U8.28 | length 2330.7
  Top Layer w10: v1@954.72,1874.72 v1(955,1875)
  Top Layer w15: U8.28@954.72,1827.44 v1@954.72,1874.72
  Top Layer w20: U3.4@1375.81,3717.87 1463.62,3717.87 R6.1@1465,3716.5 1466.5,3715 v1(1565,3715)
  Bottom Layer w15: v1(955,1875) 955,2335 1560,2940 1560,3710 v1(1565,3715)
HIGH-NODELAY: R1.1 U1.4 U8.23 | length 1866.9
  Top Layer w15: U8.23@826.77,1827.44 v1(826.77,1871.77) ; U1.4@1377.17,3245 1461.49,3245 R1.1@1465,3241.49 v1(1465,3280)
  Bottom Layer w15: v1(826.77,1871.77) 826.77,1973.23 800,2000 800,2325 1465,2990 v1(1465,3280)
IDC_FB: C39.2 R44.1 U8.38 | length 1051.3
  Top Layer w10: R44.1@1126.06,896.65 v1(1185,896.65) 1215.24,896.65 C39.2@1215.59,897 ; U8.38@1210.63,1827.44 1210.63,1804.37 v1(1235,1780)
  Bottom Layer w10: v1(1185,896.65) 1215,926.65 1215,1535 1235,1555 v1(1235,1780)
IDC_OC: C45.2 R55.1 U8.33 | length 1088.8
  Top Layer w10: v1(1080,1785) 1082.68,1787.68 U8.33@1082.68,1827.44 ; R55.1@1126.49,965 1204.65,965 C45.2@1215.59,975.94
  Bottom Layer w10: v1(1080,1785) 1085,1790 1190,1790 1205,1775 1205,1565 1185,1545 v1(1185,965)
LOW: R11.1 U5.4 U8.6 | length 2467.9
  Top Layer w15: v1(1070,2185) 1082.68,2172.32 U8.6@1082.68,2126.66
  Top Layer w20: U5.4@1377.17,4195 1461.5,4195 R11.1@1465,4191.5 1466,4192.5 v1(1527.5,4192.5)
  Bottom Layer w15: v1@1070,2190 1070,2380 1600,2910 1600,4120 v1(1527.5,4192.5)
MEDIUM: R9.1 U4.4 U8.15 | length 2342.3
  Top Layer w10: v1@852.36,2082.64 v1(855,2080)
  Top Layer w15: v1@852.36,2082.64 U8.15@852.36,2126.66
  Top Layer w20: U4.4@1377.17,3955 1463.5,3955 R9.1@1465,3956.5 1466.5,3955 v1(1520,3955)
  Bottom Layer w15: v1(855,2080) 855,2305 1520,2970 v1(1520,3955)
NetC1_1: C1.1 R2.2 U1.1 | length 160.8
  Top Layer w30: v1(965,3235) 1012.83,3235 U1.1@1022.83,3245
  Bottom Layer w30: R2.2@925,3235 v1(965,3235) C1.1@1023.86,3235
NetC2_1: C2.1 R4.2 U2.1 | length 171.6
  Top Layer w30: v1(965,3480) 1019.84,3480 U2.1@1023.94,3484.09
  Bottom Layer w30: R4.2@911.14,3485 916.14,3480 C2.1@1020,3480
NetC4_1: C4.1 C6.1 L2.3 RT1.1
NetC5_1: C5.1 F1.1 L2.4 R5.2 RV1.2
NetC5_2: C5.2 J1.3 L2.1 R8.1 RV1.1
NetC6_2: C6.2 C9.2 D4.3 L2.2
NetC8_1: C8.1 R7.2 U3.1 | length 155.5
  Top Layer w30: v1(963.07,3710) 1013.61,3710 U3.1@1021.48,3717.87
  Bottom Layer w30: R7.2@916.14,3710 v1(963.07,3710) C8.1@1010,3710
NetC11_1: C11.1 R10.2 U4.1 | length 175.8
  Top Layer w30: v1(965,3945) 1012.83,3945 U4.1@1022.83,3955
  Bottom Layer w30: R10.2@911.14,3945 v1(965,3945) C11.1@1025,3945
NetC12_1: C12.1 R12.2 U5.1 | length 153.8
  Top Layer w30: v1(965,4190) 1017.83,4190 U5.1@1022.83,4195
  Bottom Layer w30: R12.2@925,4190 v1(965,4190) C12.1@1018.86,4190
NetC13_1: C13.1 D7.1 R13.2 | length 320.8
  Top Layer w20: D7.1@3173.62,4308.95 3187.57,4295 3260,4295 3340,4215 C13.1@3340,4171.5 3346.14,4165.35 R13.2@3409.45,4165.35
NetC13_2: C13.2 C14.2 D8.1 L3.1 R14.1 | length 437.4
  Top Layer w10: D8.1@3400,3937.01 D8.1@3409.45,3946.46
  Top Layer w20: C13.2@3340,4108.5 3345.67,4114.17 C14.2@3409.45,4114.17 ; R14.1@3409.45,4216.54 3409.45,4244.45 v1(3410,4245)
  Top Layer w30: D8.1@3409.45,3946.46 C14.2@3409.45,4110
  Bottom Layer w20: v1(3410,4085) v1(3410,4245)
NetC14_1: C14.1 U7.4 | length 73.7
  Top Layer w20: C14.1@3456.69,4114.17 C14.1@3456.89,4113.98
  Top Layer w25: C14.1@3456.89,4113.98 U7.4@3530.33,4113.98
NetC15_1: C15.1 D7.2 J5.2 L3.2 R15.2 | length 561.4
  Top Layer w20: 2625,3950 2625,4015 2905,4295 2985.66,4295 D7.2@2999.61,4308.95
NetC16_1: C16.1 U6.4 | length 72.6
  Top Layer w10: C16.1@1913.39,4133.23 C16.1@1915.98,4135.83
  Top Layer w20: C16.1@1915.98,4135.83 U6.4@1984.93,4135.83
